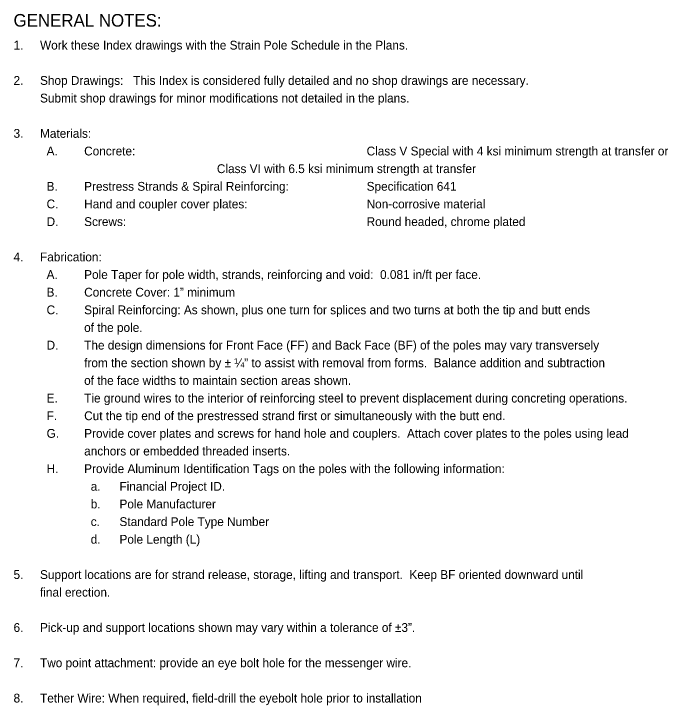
# Model space of a CAD drawing. Extents: x 10005.06 to 10010.25, y 10003.21 to 10008.69.
import ezdxf

# ---------------------------------------------------------------- set-up
doc = ezdxf.new("R2010")
doc.units = 0
doc.layers.add('DSSheetNo', color=7, linetype='Continuous')

msp = doc.modelspace()

# ---------------------------------------------------------------- texts
at = {"layer": 'DSSheetNo'}
for s, height, p in [('GENERAL NOTES:', 0.1, (10005.0547, 10008.5922)), ('1.', 0.07, (10005.0547, 10008.4102)), ('Work these Index drawings with the Strain Pole Schedule in the Plans.', 0.07, (10005.2647, 10008.4102)), ('2.', 0.07, (10005.0547, 10008.1302)), ('Shop Drawings:   This Index is considered fully detailed and no shop drawings are necessary. ', 0.07, (10005.2647, 10008.1302)), ('Submit shop drawings for minor modifications not detailed in the plans.  ', 0.07, (10005.2647, 10007.9902)), ('3.', 0.07, (10005.0547, 10007.7102)), ('Materials: ', 0.07, (10005.2647, 10007.7102)), ('  A.', 0.07, (10005.2647, 10007.5702)), ('Concrete:', 0.07, (10005.6147, 10007.5702)), ('Class V Special with 4 ksi minimum strength at transfer or', 0.07, (10007.8547, 10007.5702)), ('                                                              Class VI with 6.5 ksi minimum strength at transfer ', 0.07, (10005.0547, 10007.4302)), ('  B.', 0.07, (10005.2647, 10007.2902)), ('Prestress Strands & Spiral Reinforcing:', 0.07, (10005.6147, 10007.2902)), ('Specification 641', 0.07, (10007.8547, 10007.2902)), ('  C.', 0.07, (10005.2647, 10007.1502)), ('Hand and coupler cover plates:', 0.07, (10005.6147, 10007.1502)), ('Non-corrosive material', 0.07, (10007.8547, 10007.1502)), ('  D.', 0.07, (10005.2647, 10007.0102)), ('Screws:', 0.07, (10005.6147, 10007.0102)), ('Round headed, chrome plated ', 0.07, (10007.8547, 10007.0102)), ('4.', 0.07, (10005.0547, 10006.7302)), ('Fabrication:', 0.07, (10005.2647, 10006.7302)), ('  A.', 0.07, (10005.2647, 10006.5902)), ('Pole Taper for pole width, strands, reinforcing and void:  0.081 in/ft per face.', 0.07, (10005.6147, 10006.5902)), ('  B.', 0.07, (10005.2647, 10006.4502)), ('Concrete Cover: 1” minimum', 0.07, (10005.6147, 10006.4502)), ('  C.', 0.07, (10005.2647, 10006.3102)), ('Spiral Reinforcing: As shown, plus one turn for splices and two turns at both the tip and butt ends ', 0.07, (10005.6147, 10006.3102)), ('of the pole.', 0.07, (10005.6147, 10006.1702)), ('  D.', 0.07, (10005.2647, 10006.0302)), ('The design dimensions for Front Face (FF) and Back Face (BF) of the poles may vary transversely ', 0.07, (10005.6147, 10006.0302)), ('from the section shown by ± ¼” to assist with removal from forms.  Balance addition and subtraction ', 0.07, (10005.6147, 10005.8902)), ('of the face widths to maintain section areas shown.', 0.07, (10005.6147, 10005.7502)), ('  E.', 0.07, (10005.2647, 10005.6102)), ('Tie ground wires to the interior of reinforcing steel to prevent displacement during concreting operations.', 0.07, (10005.6147, 10005.6102)), ('  F.', 0.07, (10005.2647, 10005.4702)), ('Cut the tip end of the prestressed strand first or simultaneously with the butt end.', 0.07, (10005.6147, 10005.4702)), ('  G.', 0.07, (10005.2647, 10005.3302)), ('Provide cover plates and screws for hand hole and couplers.  Attach cover plates to the poles using lead ', 0.07, (10005.6147, 10005.3302)), ('anchors or embedded threaded inserts.  ', 0.07, (10005.6147, 10005.1902)), ('  H.', 0.07, (10005.2647, 10005.0502)), ('Provide Aluminum Identification Tags on the poles with the following information:', 0.07, (10005.6147, 10005.0502)), ('  a.', 0.07, (10005.6147, 10004.9102)), ('Financial Project ID.', 0.07, (10005.8947, 10004.9102)), ('  b.', 0.07, (10005.6147, 10004.7702)), ('Pole Manufacturer', 0.07, (10005.8947, 10004.7702)), ('  c.', 0.07, (10005.6147, 10004.6302)), ('Standard Pole Type Number', 0.07, (10005.8947, 10004.6302)), ('  d.', 0.07, (10005.6147, 10004.4902)), ('Pole Length (L)', 0.07, (10005.8947, 10004.4902)), ('5.', 0.07, (10005.0547, 10004.2102)), ('Support locations are for strand release, storage, lifting and transport.  Keep BF oriented downward until ', 0.07, (10005.2647, 10004.2102)), ('final erection.', 0.07, (10005.2647, 10004.0702)), ('6.', 0.07, (10005.0547, 10003.7902)), ('Pick-up and support locations shown may vary within a tolerance of ±3”.', 0.07, (10005.2647, 10003.7902)), ('7.', 0.07, (10005.0547, 10003.5102)), ('Two point attachment: provide an eye bolt hole for the messenger wire.', 0.07, (10005.2647, 10003.5102)), ('Tether Wire: When required, field-drill the eyebolt hole prior to installation', 0.07, (10005.2647, 10003.2302)), ('8.', 0.07, (10005.0547, 10003.2302))]:
    msp.add_text(s, height=height, dxfattribs=at).set_placement(p)

doc.saveas('drawing.dxf')
